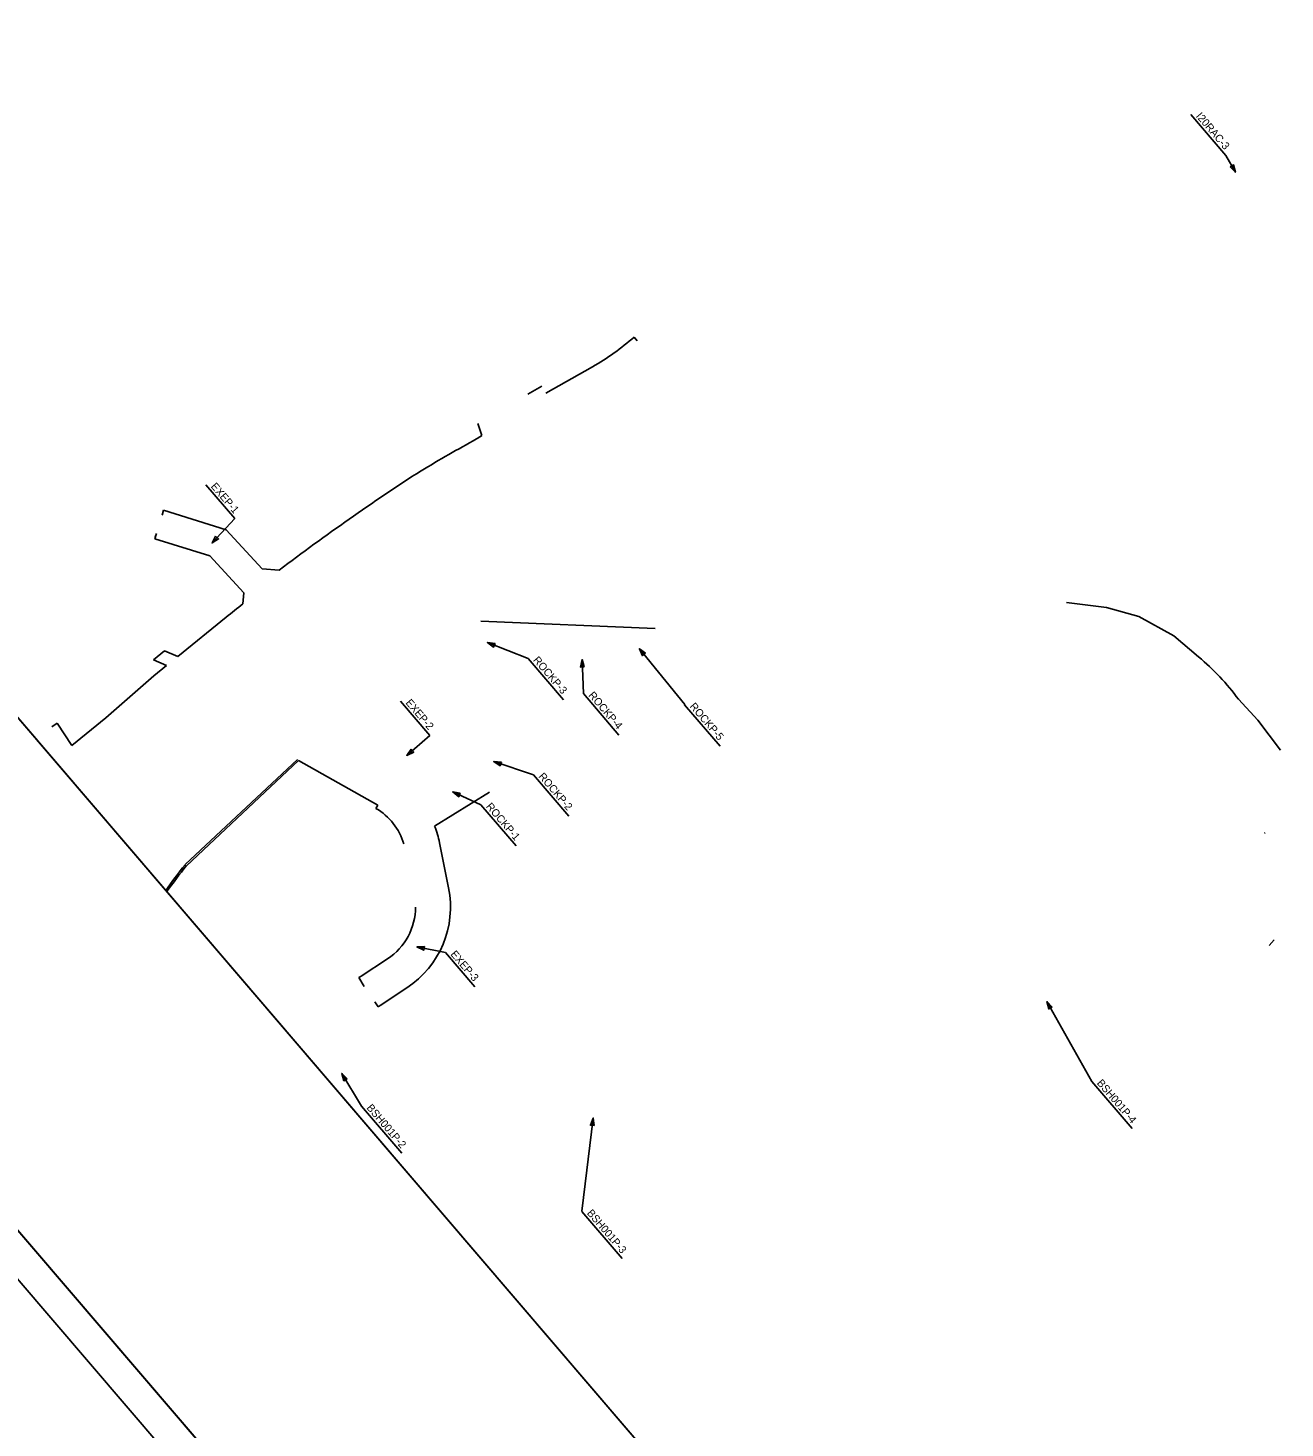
# Model space of a CAD drawing. Extents: x 1941897 to 1978064, y 805467 to 836604.
# Drawn here: x 1952730 to 1956688, y 817143 to 821550 of the extents above; entities that cross this region are included whole.
import ezdxf

# ---------------------------------------------------------------- set-up
doc = ezdxf.new("R2010")
doc.units = 0
for name, color, linetype in [('RD_EX_H20_TX', 7, 'Continuous'), ('RD_PD_Control_Access', 7, 'Continuous'), ('RD_PD_RW', 7, 'Continuous'), ('RD_SHT_Bndy', 7, 'Continuous'), ('RD_SHT_IplotShp', 7, 'Continuous'), ('RD_TX_RoadID', 7, 'Continuous')]:
    doc.layers.add(name, color=color, linetype=linetype)

msp = doc.modelspace()

# ---------------------------------------------------------------- linework, layer by layer
at = {"layer": 'RD_EX_H20_TX'}
for points in [[(1963151.2, 810860.3), (1959509.3, 815114.3), (1958096.8, 813905.1), (1957040.5, 814307.7), (1947588.1, 825348.6), (1952108, 829218.2), (1965848, 813169.1)], [(1963151.2, 810860.3), (1959509.3, 815114.3), (1958096.8, 813905.1), (1957040.5, 814307.7), (1947588.1, 825348.6), (1952108, 829218.2), (1965848, 813169.1)], [(1963151.2, 810860.3), (1959509.3, 815114.3), (1958096.8, 813905.1), (1957040.5, 814307.7), (1947588.1, 825348.6), (1952108, 829218.2), (1965848, 813169.1)], [(1963151.2, 810860.3), (1959509.3, 815114.3), (1958096.8, 813905.1), (1957040.5, 814307.7), (1949323.3, 823321.8), (1953668.8, 827395), (1965848, 813169.1)], [(1963151.2, 810860.3), (1959509.3, 815114.3), (1958096.8, 813905.1), (1957040.5, 814307.7), (1949323.3, 823321.8), (1953668.8, 827395), (1965848, 813169.1)], [(1963151.2, 810860.3), (1959509.3, 815114.3), (1958096.8, 813905.1), (1957040.5, 814307.7), (1949323.3, 823321.8), (1953668.8, 827395), (1965848, 813169.1)]]:
    msp.add_lwpolyline(points, close=True, dxfattribs=at)
at = {"layer": 'RD_PD_Control_Access'}
for p, q in [((1954156, 819683.3), (1954704.4, 819659.7)), ((1953225.4, 818917), (1953578.7, 819247.9))]:
    msp.add_line(p, q, dxfattribs=at)
for points in [[(1956000, 819742), (1956126.1, 819726.2), (1956227.8, 819698.1), (1956337.8, 819636.5), (1956416, 819570.4)], [(1956541.5, 819437.1), (1956602.2, 819371), (1956673.7, 819277.1)]]:
    msp.add_lwpolyline(points, dxfattribs=at)
for centre, radius, start, end in [((1955921.3, 818979), 771, 36.4561, 50.0877), ((1954759.7, 817697.4), 1960, 141.5383, 144.4976)]:
    msp.add_arc(centre, radius, start, end, dxfattribs=at)
at = {"layer": 'RD_PD_RW'}
for p, q in [((1954638.6, 820577.3), (1954648.5, 820566)), ((1954507.7, 820484.3), (1954360.7, 820401.2)), ((1954348.4, 820422.9), (1954304.2, 820398)), ((1954146.2, 820305.9), (1954159.3, 820267.1)), ((1953157.3, 820032.6), (1953152.2, 820016.3)), ((1953157.3, 820032.6), (1953354.3, 819970.5)), ((1953129.3, 819942.8), (1953134.4, 819959)), ((1953354.3, 819970.5), (1953467, 819848.3)), ((1953129.3, 819942.8), (1953302.2, 819888.3)), ((1953130.9, 819948.2), (1953131.9, 819951.6)), ((1953130.9, 819948.2), (1953131.9, 819951.6)), ((1953302.2, 819888.3), (1953409.5, 819771.9)), ((1953467, 819848.3), (1953521.3, 819843.5)), ((1953406.9, 819738), (1953409.5, 819771.9)), ((1953201.6, 819571.9), (1953354.4, 819695.9)), ((1953125.3, 819561.5), (1953160.3, 819589.9)), ((1953166.6, 819543.5), (1953125.3, 819561.5)), ((1953201.6, 819571.9), (1953160.3, 819589.9)), ((1953126.3, 819510.8), (1953166.6, 819543.5)), ((1952975.7, 819378.9), (1953126.3, 819510.8)), ((1952821.7, 819361.8), (1952805.1, 819350.6)), ((1952868.7, 819292.1), (1952821.7, 819361.8)), ((1952868.7, 819292.1), (1952975.7, 819378.9)), ((1953228.9, 818913.3), (1953582.1, 819244.3)), ((1953831.3, 819103.5), (1953582.1, 819244.3)), ((1954183.2, 819144.9), (1954010.6, 819037.4)), ((1953825.7, 819093.6), (1953831.3, 819103.5)), ((1956623.4, 819016.2), (1956625.1, 819016.3)), ((1954025.9, 818985.7), (1954054.4, 818843.5)), ((1956654.2, 818680.3), (1956638.1, 818662.1)), ((1953862.6, 818620.4), (1953779, 818565.5)), ((1953772.2, 818560.9), (1953789.1, 818532.7)), ((1953923, 818528.5), (1953839.5, 818473.6)), ((1953832.6, 818469), (1953822.1, 818485))]:
    msp.add_line(p, q, dxfattribs=at)
for centre, radius, start, end in [((1954121.2, 821167.6), 785, 299.4894, 311.2327), ((1957799.2, 814217.8), 7060, 121.03534, 121.19571), ((1957576.1, 814078.2), 7068.7, 119.06201, 120.69471), ((1957799.2, 814217.8), 7067.5, 122.82841, 127.24984), ((1957799.2, 814217.8), 7054.5, 128.50868, 129.05502), ((1953726.8, 818925.6), 195, 16.763, 59.5291), ((1953726.8, 818925.6), 305, 11.3656, 21.5171), ((1954759.7, 817697.4), 1955, 141.5383, 144.5339), ((1953755.4, 818783.4), 305, 303.331, 11.3656), ((1953755.4, 818783.4), 195, 303.331, 359.902), ((1954029, 818185.3), 455, 123.331, 124.3662), ((1954029, 818185.3), 345, 123.331, 124.6958)]:
    msp.add_arc(centre, radius, start, end, dxfattribs=at)
at = {"layer": 'RD_SHT_Bndy'}
for points in [[(1960707.9, 808409.5), (1943668.8, 828312), (1948986.3, 832864.4), (1966025.3, 812961.9)], [(1946512.2, 824990.8), (1956970, 812775.5), (1957767.7, 813458.3), (1947309.9, 825673.6)]]:
    msp.add_lwpolyline(points, close=True, dxfattribs=at)
at = {"layer": 'RD_SHT_IplotShp'}
msp.add_lwpolyline([(1960696.9, 808268.5), (1943527.9, 828323), (1948997.3, 833005.4), (1966166.3, 812950.9)], close=True, dxfattribs=at)
at = {"layer": 'RD_TX_RoadID'}
for p, q in [((1956501.9, 821149.6), (1956391.7, 821278.3)), ((1953381.4, 820005.8), (1953290, 820112.6)), ((1954416.3, 819435.5), (1954304.8, 819565.8)), ((1953995.9, 819323.1), (1953903.1, 819431.3)), ((1954590.9, 819324.1), (1954478.8, 819455)), ((1954909.6, 819289.3), (1954797.6, 819420.1)), ((1954433.4, 819068.9), (1954321.6, 819199.6)), ((1954266.9, 818975.8), (1954156.4, 819104.9)), ((1954137, 818531.9), (1954044.6, 818639.8)), ((1956207.1, 818085.6), (1956079.8, 818234.3)), ((1953907.5, 818007.8), (1953780.4, 818156.3)), ((1954600.9, 817676.8), (1954474.1, 817824.9))]:
    msp.add_line(p, q, dxfattribs=at)
for points in [[(1956501.9, 821149.6), (1956531.9, 821096.4)], [(1953381.4, 820005.8), (1953309.6, 819929.2)], [(1954304.8, 819565.8), (1954176.7, 819615.6)], [(1954478.8, 819455), (1954474.8, 819562.1)], [(1954798.1, 819420.6), (1954655.3, 819596.1)], [(1953995.9, 819323.1), (1953922.9, 819260.4)], [(1954321.6, 819199.6), (1954196.8, 819240.9)], [(1954156.4, 819104.9), (1954067.8, 819145.5)], [(1954044.6, 818639.8), (1953954.7, 818657.6)], [(1956079.8, 818234.3), (1955938.2, 818485.5)], [(1953780.1, 818156.6), (1953718.3, 818259.3)], [(1954473.7, 817825.4), (1954509.9, 818118.6)]]:
    msp.add_lwpolyline(points, dxfattribs=at)
for points in [[(1956515.1, 821113.6), (1956531.9, 821096.4), (1956525.9, 821119.7)], [(1953320.9, 819950.4), (1953309.6, 819929.2), (1953330, 819941.9)], [(1954200.6, 819613), (1954176.7, 819615.6), (1954196.1, 819601.4)], [(1954481.8, 819539.2), (1954474.8, 819562.1), (1954469.4, 819538.7)], [(1954674.7, 819582), (1954655.3, 819596.1), (1954665.1, 819574.2)], [(1953936.4, 819280.2), (1953922.9, 819260.4), (1953944.5, 819270.8)], [(1954220.7, 819239.5), (1954196.8, 819240.9), (1954216.8, 819227.7)], [(1954091.4, 819141.5), (1954067.8, 819145.5), (1954086.2, 819130.2)], [(1953978.7, 818659.2), (1953954.7, 818657.6), (1953976.3, 818647)], [(1955955, 818468.3), (1955938.2, 818485.5), (1955944.2, 818462.2)], [(1953735.6, 818242.6), (1953718.3, 818259.3), (1953724.9, 818236.2)], [(1954513.2, 818094.9), (1954509.9, 818118.6), (1954500.9, 818096.4)]]:
    msp.add_lwpolyline(points, close=True, dxfattribs=at)

# ---------------------------------------------------------------- texts
for s, p in [('I20RAC-3', (1956406.1, 821272.2)), ('EXEP-1', (1953304.4, 820106.5)), ('ROCKP-3', (1954319.2, 819559.7)), ('EXEP-2', (1953917.6, 819425.3)), ('ROCKP-4', (1954493.3, 819448.9)), ('ROCKP-5', (1954812, 819414)), ('ROCKP-2', (1954336, 819193.5)), ('ROCKP-1', (1954170.8, 819098.8)), ('EXEP-3', (1954059, 818633.7)), ('BSH001P-4', (1956094.2, 818228.2)), ('BSH001P-2', (1953794.8, 818150.2)), ('BSH001P-3', (1954488.5, 817818.8))]:
    msp.add_text(s, height=24, rotation=310.5675, dxfattribs=at).set_placement(p)

doc.saveas('drawing.dxf')
